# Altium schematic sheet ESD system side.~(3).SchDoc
size A3; SheetNumber: 14; SheetTotal: 14
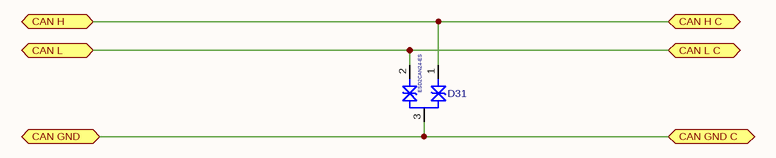
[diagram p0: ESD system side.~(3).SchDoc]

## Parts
D31  ESD2CAN24-ES  [SOT-23 123]

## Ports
CAN GND (bidir, see Arhitecture[6B], BMS[8B], MCU[8B]), CAN GND C (bidir, see Arhitecture[7B]), CAN H (bidir, see Arhitecture[6B], BMS[8B], MCU[8A]), CAN H C (bidir, see Arhitecture[7B]), CAN L (bidir, see Arhitecture[6B], BMS[8B], MCU[8B]), CAN L C (bidir, see Arhitecture[7B])

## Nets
CAN GND: D31.3 ; port CAN GND, port CAN GND C
CAN H: D31.1 ; port CAN H, port CAN H C
CAN L: D31.2 ; port CAN L, port CAN L C

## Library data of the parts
D31 = ESD2CAN24-ES: ESD TVS CAN; Manufacturer: ElecSuper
